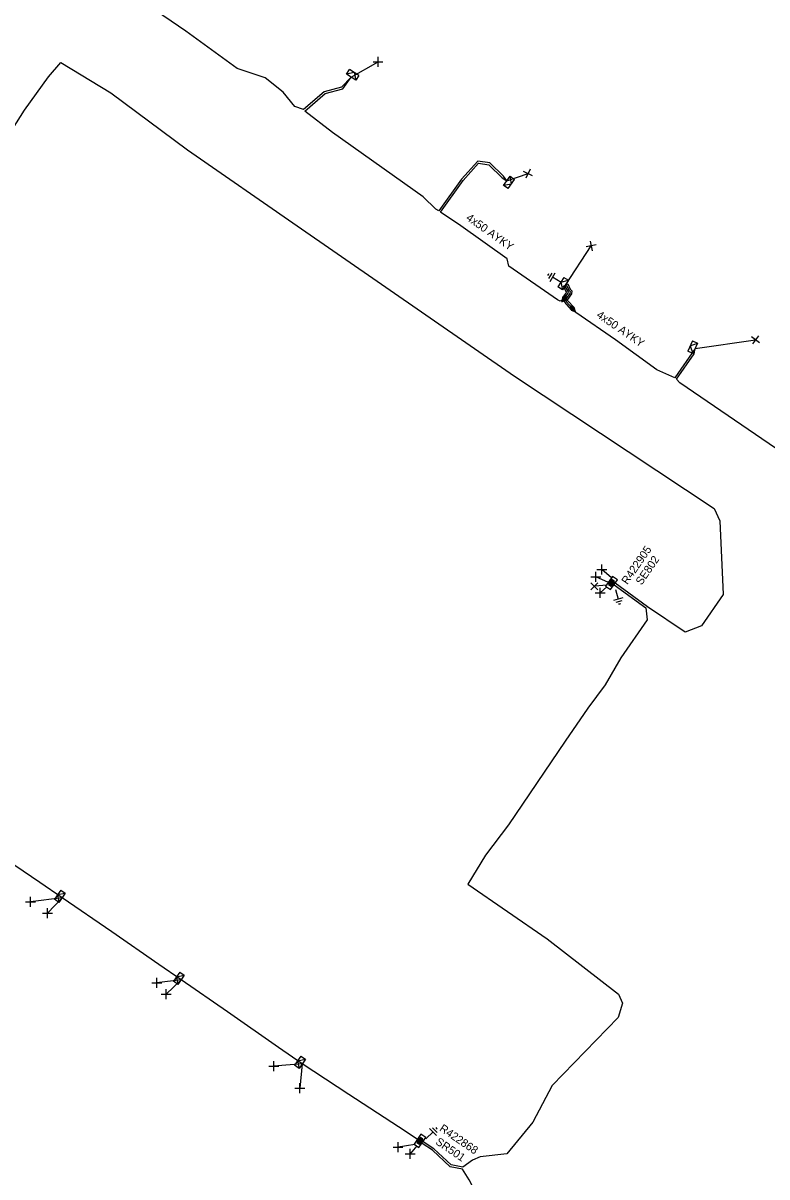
# Model space of a CAD drawing. Extents: x -540466 to -537383, y -1184038 to -1179972.
# Drawn here: x -538591.5 to -538498.5, y -1181344 to -1181199.8 of the extents above; entities that cross this region are included whole.
import ezdxf

# ---------------------------------------------------------------- set-up
doc = ezdxf.new("R2010")
doc.units = 0
for name, color, linetype in [('Vrstva 1', 7, 'Continuous'), ('Vrstva 14', 7, 'Continuous'), ('Vrstva 15', 7, 'Continuous'), ('Vrstva 19', 7, 'Continuous'), ('Vrstva 20', 7, 'Continuous'), ('Vrstva 28', 7, 'Continuous'), ('Vrstva 29', 7, 'Continuous'), ('Vrstva 30', 7, 'Continuous'), ('Vrstva 31', 7, 'Continuous'), ('Vrstva 34', 7, 'Continuous'), ('Vrstva 4', 7, 'Continuous'), ('Vrstva 5', 7, 'Continuous'), ('Vrstva 59', 7, 'Continuous'), ('Vrstva 6', 7, 'Continuous'), ('Vrstva 8', 7, 'Continuous'), ('Vrstva 9', 7, 'Continuous')]:
    doc.layers.add(name, color=color, linetype=linetype)

# ---------------------------------------------------------------- blocks, each defined once
blk = doc.blocks.new('NN870')
at = {"layer": 'Vrstva 4'}
for points in [[(0, -0.25), (0.5, 0), (0, 0.25), (-0.5, 0), (0, -0.25)], [(0.37, 0), (0, 0.19), (-0.36, 0), (0, -0.19), (0.37, 0)], [(0.24, 0), (0, 0.12), (-0.25, 0), (0, -0.12), (0.24, 0)], [(0.12, 0), (0, 0.06), (-0.13, 0), (0, -0.06), (0.12, 0)]]:
    blk.add_lwpolyline(points, dxfattribs=at)
blk = doc.blocks.new('NN800')
at = {"layer": 'Vrstva 1'}
for points in [[(-0.44, 0.44), (0.44, -0.44)], [(-0.44, -0.44), (0.44, 0.44)]]:
    blk.add_lwpolyline(points, dxfattribs=at)
blk = doc.blocks.new('NN620')
at = {"layer": 'Vrstva 8'}
for points in [[(0.75, 0), (-0.75, 0)], [(-0.75, 0), (-0.75, -0.75)], [(0.75, -0.75), (0.75, 0)], [(-0.75, -0.75), (0.75, -0.75)], [(0.37, -0.18), (-0.38, -0.18)], [(-0.38, -0.18), (-0.38, -0.56)], [(-0.38, -0.56), (0.37, -0.56)], [(0.32, -0.23), (-0.33, -0.23)], [(-0.33, -0.23), (-0.33, -0.51)], [(-0.33, -0.51), (0.32, -0.51)], [(0.27, -0.27), (-0.28, -0.27)], [(-0.28, -0.27), (-0.28, -0.46)], [(-0.28, -0.46), (0.27, -0.46)], [(0.23, -0.32), (-0.23, -0.32)], [(-0.23, -0.32), (-0.23, -0.42)], [(-0.23, -0.42), (0.23, -0.42)], [(-0.19, -0.37), (0.19, -0.37)], [(0.23, -0.42), (0.23, -0.32)], [(0.27, -0.46), (0.27, -0.27)], [(0.32, -0.51), (0.32, -0.23)], [(0.37, -0.56), (0.37, -0.18)]]:
    blk.add_lwpolyline(points, dxfattribs=at)
blk = doc.blocks.new('NN630')
at = {"layer": 'Vrstva 9'}
for points in [[(0, -0.7), (-0.7, 0)], [(-0.7, -0.7), (-0.7, 0), (0.7, 0), (0.7, -0.7)], [(-0.7, -0.7), (0.7, -0.7)], [(0, -0.7), (0.7, 0)]]:
    blk.add_lwpolyline(points, dxfattribs=at)
blk = doc.blocks.new('NN810')
at = {"layer": 'Vrstva 14'}
for points in [[(0, -0.64), (0, -1.89)], [(0.63, -1.89), (-0.62, -1.89)], [(0.39, -2.2), (-0.4, -2.2)], [(0, -2.52), (-0.12, -2.52)], [(0.14, -2.52), (0, -2.52)]]:
    blk.add_lwpolyline(points, dxfattribs=at)

msp = doc.modelspace()

# ---------------------------------------------------------------- linework, layer by layer
at = {"layer": 'Vrstva 20'}
for points in [[(-538523.41, -1181232.42), (-538523.08, -1181233.07), (-538522.9, -1181233.29), (-538522.94, -1181233.66), (-538523.53, -1181234.48), (-538524.01, -1181234.12), (-538523.53, -1181233.46), (-538523.58, -1181233.39), (-538523.95, -1181232.7)], [(-538522.92, -1181235.64), (-538523.76, -1181234.71), (-538523.94, -1181234.4), (-538523.6, -1181234.2), (-538523.44, -1181234.47), (-538522.62, -1181235.38)]]:
    msp.add_lwpolyline(points, close=True, dxfattribs=at)
at = {"layer": 'Vrstva 5'}
for points in [[(-538523.85, -1181234.24), (-538523.95, -1181234.38), (-538524.35, -1181234.55), (-538524.69, -1181234.4), (-538530.78, -1181230.2), (-538530.99, -1181229.27), (-538536.77, -1181225.17), (-538539.31, -1181223.44), (-538536.48, -1181219.5), (-538534.55, -1181217.34), (-538533.27, -1181217.54), (-538531.59, -1181219.14), (-538531.01, -1181219.53), (-538531.44, -1181218.95), (-538533.15, -1181217.3), (-538534.65, -1181217.08), (-538536.68, -1181219.34), (-538539.51, -1181223.3), (-538539.89, -1181223.06), (-538541.48, -1181221.54), (-538552.78, -1181213.48), (-538556.27, -1181210.81), (-538553.72, -1181208.63), (-538551.5, -1181208.05), (-538550.48, -1181206.57), (-538551.66, -1181207.83), (-538553.84, -1181208.41), (-538556.43, -1181210.62), (-538557.52, -1181210.23), (-538558.98, -1181208.47), (-538561.22, -1181206.66), (-538564.69, -1181205.48), (-538571.14, -1181200.82), (-538587.07, -1181189.91)], [(-538594.21, -1181218.67), (-538595.41, -1181217.15), (-538591.28, -1181210.69), (-538588.29, -1181206.54), (-538586.75, -1181204.74), (-538580.48, -1181208.54), (-538570.92, -1181215.64), (-538557.23, -1181225.17), (-538530.05, -1181243.93), (-538505.09, -1181260.46), (-538504.4, -1181262.01), (-538504, -1181271.23), (-538506.68, -1181275.14), (-538508.73, -1181275.95), (-538513.42, -1181272.77), (-538517.47, -1181269.81)], [(-538523.85, -1181234.24), (-538523.37, -1181233.58), (-538523.31, -1181233.41), (-538523.41, -1181233.28), (-538523.69, -1181232.76), (-538523.68, -1181232.56), (-538523.51, -1181232.66), (-538523.25, -1181233.18), (-538523.11, -1181233.35), (-538523.13, -1181233.59), (-538523.71, -1181234.39), (-538523.6, -1181234.59), (-538522.77, -1181235.51)], [(-538420.27, -1181293.15), (-538423.17, -1181296.41), (-538426.28, -1181294.55), (-538430.59, -1181291.84), (-538439.07, -1181286.61), (-538454.4, -1181277.11), (-538464.95, -1181270.76), (-538473.5, -1181265.11), (-538476.03, -1181263.27), (-538477.32, -1181263.08), (-538480.1, -1181264.32), (-538481.92, -1181263.55), (-538494.81, -1181254.72), (-538509.41, -1181244.76), (-538509.83, -1181244.31), (-538507.6, -1181241.16), (-538507.48, -1181240.47), (-538510.03, -1181244.17), (-538512.27, -1181243.13), (-538517.42, -1181239.41), (-538522.4, -1181235.98), (-538522.67, -1181235.74), (-538522.77, -1181235.51)], [(-538517.61, -1181270.02), (-538513.65, -1181272.91), (-538513.47, -1181274.41), (-538516.77, -1181279.13), (-538518.72, -1181282.52), (-538520.9, -1181285.45), (-538523.71, -1181289.54), (-538530.82, -1181300.01), (-538533.68, -1181303.79), (-538535.9, -1181307.43), (-538525.96, -1181314.26), (-538517.06, -1181321.18), (-538516.54, -1181322.29), (-538517.09, -1181324.08), (-538525.35, -1181332.59), (-538527.76, -1181337.16), (-538531.02, -1181341.12), (-538534.34, -1181341.5), (-538535.32, -1181341.92), (-538536.53, -1181342.8), (-538537.96, -1181342.5), (-538540.15, -1181340.48), (-538541.47, -1181339.61)], [(-538542.22, -1181339.29), (-538544.57, -1181337.74), (-538550.74, -1181333.69), (-538556.58, -1181329.88), (-538559.53, -1181327.83), (-538565.91, -1181323.39), (-538571.71, -1181319.38), (-538574.49, -1181317.46), (-538580.38, -1181313.4), (-538586.58, -1181309.13), (-538589.38, -1181307.22), (-538595.76, -1181302.87), (-538601.51, -1181298.96), (-538604.25, -1181297.07), (-538610.55, -1181292.73), (-538616.65, -1181288.54), (-538619.28, -1181286.73), (-538625.05, -1181282.75), (-538631.33, -1181278.43)], [(-538538.94, -1181394.04), (-538539.66, -1181391.77), (-538540.85, -1181387.34), (-538543.34, -1181383.87), (-538545.16, -1181379.86), (-538547.41, -1181376.9), (-538549.5, -1181371.14), (-538550.46, -1181367.89), (-538550.06, -1181366.31), (-538548.1, -1181364), (-538545.65, -1181360.71), (-538542.47, -1181356.68), (-538540.22, -1181353.2), (-538535.63, -1181346.65), (-538535.24, -1181345.33), (-538535.74, -1181344.38), (-538536.57, -1181343.05), (-538538.08, -1181342.73), (-538540.32, -1181340.66), (-538541.61, -1181339.82)]]:
    msp.add_lwpolyline(points, dxfattribs=at)
at = {"layer": 'Vrstva 59'}
for points in [[(-538550.48, -1181206.57), (-538547.11, -1181204.66)], [(-538531.01, -1181219.53), (-538528.36, -1181218.63)], [(-538523.68, -1181232.56), (-538520.48, -1181227.66)], [(-538507.48, -1181240.47), (-538499.93, -1181239.41)], [(-538517.94, -1181269.16), (-538519.14, -1181268.09)], [(-538518.32, -1181269.71), (-538519.9, -1181269)], [(-538518.48, -1181270.04), (-538520.07, -1181270.19)], [(-538518.52, -1181270.27), (-538519.34, -1181271.01)], [(-538586.58, -1181309.13), (-538590.54, -1181309.62)], [(-538586.58, -1181309.13), (-538588.42, -1181311.06)], [(-538571.71, -1181319.38), (-538574.74, -1181319.74)], [(-538571.71, -1181319.38), (-538573.59, -1181321.18)], [(-538556.58, -1181329.88), (-538560.11, -1181330.18)], [(-538556.58, -1181329.88), (-538556.89, -1181332.92)], [(-538542.49, -1181339.95), (-538544.61, -1181340.3)], [(-538542.27, -1181340.11), (-538543.1, -1181341.11)]]:
    msp.add_lwpolyline(points, dxfattribs=at)

# ---------------------------------------------------------------- block references
at = {"layer": 'Vrstva 15'}
for p, rotation in [((-538523.68, -1181232.56), -121.76210589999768), ((-538517.63, -1181270), 16.168035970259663), ((-538541.57, -1181339.72), 135)]:
    msp.add_blockref('NN810', p, dxfattribs=dict(at, rotation=rotation))
at = {"layer": 'Vrstva 19'}
for p, rotation in [((-538523.85, -1181234.24), 54.24611269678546), ((-538522.77, -1181235.51), 132.05595357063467)]:
    msp.add_blockref('NN870', p, dxfattribs=dict(at, rotation=rotation))
at = {"layer": 'Vrstva 28'}
for p, rotation in [((-538517.63, -1181270), -124.53989441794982), ((-538541.57, -1181339.72), -124.37427220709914)]:
    msp.add_blockref('NN620', p, dxfattribs=dict(at, rotation=rotation))
at = {"layer": 'Vrstva 31'}
for p, rotation in [((-538550.48, -1181206.57), 146.52216107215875), ((-538531.01, -1181219.53), 55.262205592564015), ((-538523.68, -1181232.56), -121.83528242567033), ((-538507.48, -1181240.47), -115.42476944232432), ((-538586.58, -1181309.13), -124.4146027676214), ((-538571.71, -1181319.38), -124.41460282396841), ((-538556.58, -1181329.88), -124.4146027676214)]:
    msp.add_blockref('NN630', p, dxfattribs=dict(at, rotation=rotation))
at = {"layer": 'Vrstva 34'}
for p, rotation in [((-538547.11, -1181204.66), 45), ((-538528.36, -1181218.63), -161.29265469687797), ((-538520.48, -1181227.66), -123.1676537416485), ((-538499.93, -1181239.4), -171.98565104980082), ((-538519.14, -1181268.09), 44.99999995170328), ((-538519.9, -1181269), 45), ((-538519.34, -1181271.01), 45), ((-538590.54, -1181309.62), 45), ((-538588.42, -1181311.06), 45), ((-538574.74, -1181319.74), 45), ((-538573.59, -1181321.18), 45), ((-538560.11, -1181330.18), 45), ((-538556.89, -1181332.92), 45.00000009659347), ((-538544.61, -1181340.3), 45.00000009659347), ((-538543.1, -1181341.11), 45)]:
    msp.add_blockref('NN800', p, dxfattribs=dict(at, rotation=rotation))
msp.add_blockref('NN800', (-538520.07, -1181270.19), dxfattribs=at)

# ---------------------------------------------------------------- texts
at = {"layer": 'Vrstva 29'}
for s, rotation, p in [('R422905', 55.46, (-538515.95, -1181270.06)), ('R422868', 325.626, (-538539.52, -1181338.17))]:
    msp.add_text(s, height=1, rotation=rotation, dxfattribs=at).set_placement(p)
at = {"layer": 'Vrstva 30'}
for s, rotation, p in [('SE802', 55.46, (-538514.18, -1181270.13)), ('SR501', 325.626, (-538540.01, -1181339.83))]:
    msp.add_text(s, height=1, rotation=rotation, dxfattribs=at).set_placement(p)
at = {"layer": 'Vrstva 6'}
for rotation, p in [(324.65, (-538536.19, -1181224.35)), (325.419, (-538519.89, -1181236.5))]:
    msp.add_text('4x50 AYKY', height=1, rotation=rotation, dxfattribs=at).set_placement(p)

doc.saveas('drawing.dxf')
